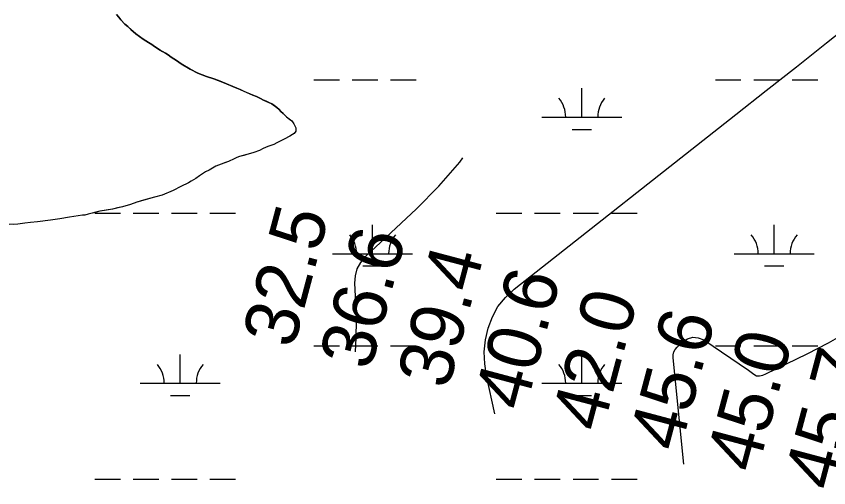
# Model space of a CAD drawing. Extents: x 3192927 to 3230760, y 831141 to 856475.
# Drawn here: x 3214685 to 3215700, y 837451 to 838041 of the extents above; entities that cross this region are included whole.
import ezdxf

# ---------------------------------------------------------------- set-up
doc = ezdxf.new("R2010")
doc.units = 0
for name, color, linetype in [('V-RIVR-RANG', 7, 'Continuous'), ('V-SITE-VEGE', 7, 'Continuous'), ('V-TOPO-MAJR', 7, 'Continuous'), ('V-TOPO-MINR', 7, 'Continuous'), ('V-TOPO-SHOR', 7, 'Continuous'), ('V-WETL-SWMP', 7, 'Continuous')]:
    doc.layers.add(name, color=color, linetype=linetype)

msp = doc.modelspace()

# ---------------------------------------------------------------- linework, layer by layer
at = {"layer": 'V-SITE-VEGE'}
for p, q in [((3214809.9, 838042.9), (3214812.9, 838039.5)), ((3214812.9, 838039.5), (3214815.5, 838036.4)), ((3214815.5, 838036.4), (3214820.3, 838031)), ((3214820.3, 838031), (3214823.9, 838027.7)), ((3214823.9, 838027.7), (3214834.1, 838018.6)), ((3214834.1, 838018.6), (3214838.7, 838015.2)), ((3214838.7, 838015.2), (3214843.3, 838012)), ((3214843.3, 838012), (3214849.9, 838007.7)), ((3214849.9, 838007.7), (3214853.9, 838005.3)), ((3214853.9, 838005.3), (3214857.3, 838003)), ((3214857.3, 838003), (3214867.3, 837996.6)), ((3214867.3, 837996.6), (3214871.1, 837994.5)), ((3214871.1, 837994.5), (3214874.5, 837992.3)), ((3214874.5, 837992.3), (3214878.1, 837989.7)), ((3214878.1, 837989.7), (3214885.1, 837985.4)), ((3214885.1, 837985.4), (3214890.9, 837981.2)), ((3214890.9, 837981.2), (3214901.9, 837974.5)), ((3214901.9, 837974.5), (3214911.6, 837969.6)), ((3214911.6, 837969.6), (3214922.6, 837965.3)), ((3214922.6, 837965.3), (3214931.6, 837962.4)), ((3214931.6, 837962.4), (3214942.4, 837958.2)), ((3214942.4, 837958.2), (3214964.5, 837949)), ((3214964.5, 837949), (3214976.5, 837943.9)), ((3214976.5, 837943.9), (3214980.3, 837942.1)), ((3214980.3, 837942.1), (3214984.9, 837940.2)), ((3214984.9, 837940.2), (3214989.9, 837937.8)), ((3214989.9, 837937.8), (3214993.5, 837935.8)), ((3214993.5, 837935.8), (3215000.5, 837932.9)), ((3215000.5, 837932.9), (3215004.1, 837931.1)), ((3215004.1, 837931.1), (3215010.3, 837926.6)), ((3215010.3, 837926.6), (3215013.3, 837924)), ((3215013.3, 837924), (3215015.5, 837921.6)), ((3215015.5, 837921.6), (3215020.1, 837917.3)), ((3215020.1, 837917.3), (3215022.5, 837914.9)), ((3215022.5, 837914.9), (3215028.9, 837910)), ((3215028.9, 837910), (3215031.7, 837906.2)), ((3215031.7, 837906.2), (3215033.9, 837901.4)), ((3215033.9, 837901.4), (3215034.1, 837897)), ((3215026.4, 837890.8), (3215019.4, 837887.1)), ((3215031.8, 837894), (3215026.4, 837890.8)), ((3215034.1, 837897), (3215031.8, 837894)), ((3215006.5, 837880.5), (3214999.1, 837877.8)), ((3215010.4, 837882.3), (3215006.5, 837880.5)), ((3215019.4, 837887.1), (3215010.4, 837882.3)), ((3214981.7, 837870.3), (3214977.4, 837869.1)), ((3214988.7, 837873), (3214981.7, 837870.3)), ((3214993.3, 837875.4), (3214988.7, 837873)), ((3214999.1, 837877.8), (3214993.3, 837875.4)), ((3214949.8, 837859.3), (3214940.7, 837855.9)), ((3214957, 837862.4), (3214949.8, 837859.3)), ((3214960.4, 837864), (3214957, 837862.4)), ((3214963.8, 837865.2), (3214960.4, 837864)), ((3214973, 837867.7), (3214963.8, 837865.2)), ((3214977.4, 837869.1), (3214973, 837867.7)), ((3214934.1, 837853.1), (3214925.9, 837848.4)), ((3214940.7, 837855.9), (3214934.1, 837853.1)), ((3214913.8, 837841.2), (3214909, 837837.9)), ((3214917.5, 837843.6), (3214913.8, 837841.2)), ((3214921.3, 837846.2), (3214917.5, 837843.6)), ((3214925.9, 837848.4), (3214921.3, 837846.2)), ((3214900, 837832.5), (3214890.2, 837827.8)), ((3214903.4, 837834.5), (3214900, 837832.5)), ((3214906, 837836.3), (3214903.4, 837834.5)), ((3214909, 837837.9), (3214906, 837836.3)), ((3214880.9, 837823), (3214866.9, 837816.9)), ((3214890.2, 837827.8), (3214880.9, 837823)), ((3214857.5, 837814.5), (3214835.2, 837808.1)), ((3214866.9, 837816.9), (3214857.5, 837814.5)), ((3214804.7, 837799.6), (3214788.9, 837796.9)), ((3214817.6, 837802.4), (3214804.7, 837799.6)), ((3214827.6, 837805.5), (3214817.6, 837802.4)), ((3214835.2, 837808.1), (3214827.6, 837805.5)), ((3214751.2, 837789.7), (3214739, 837787.6)), ((3214767.3, 837792), (3214751.2, 837789.7)), ((3214770.5, 837792), (3214767.3, 837792)), ((3214774.5, 837793.4), (3214770.5, 837792)), ((3214788.9, 837796.9), (3214774.5, 837793.4)), ((3214686.5, 837780.7), (3214675.9, 837780.2)), ((3214695.3, 837782), (3214686.5, 837780.7)), ((3214702.4, 837782.8), (3214695.3, 837782)), ((3214711.2, 837783.6), (3214702.4, 837782.8)), ((3214727.2, 837785.7), (3214711.2, 837783.6)), ((3214739, 837787.6), (3214727.2, 837785.7))]:
    msp.add_line(p, q, dxfattribs=at)
at = {"layer": 'V-TOPO-MAJR'}
msp.add_lwpolyline([(3215108.5, 837621.3), (3215109.5, 837638.5), (3215109.7, 837660.6), (3215109.1, 837682.6), (3215107.8, 837707.1), (3215108.6, 837716.4), (3215110.9, 837725.1), (3215115.3, 837732.9), (3215121.2, 837740.2), (3215184.8, 837799.9), (3215212.8, 837828.5), (3215239, 837858.5), (3215242.7, 837863.6)], dxfattribs=at)
at = {"layer": 'V-TOPO-MINR'}
for points in [[(3215282.7, 837543.5), (3215272.3, 837591.3), (3215270.2, 837606.2), (3215269.6, 837621.2), (3215271.2, 837636), (3215274.3, 837650.8), (3215279.7, 837664.8), (3215286.7, 837677.7), (3215296, 837689), (3215306.8, 837699.4), (3215584, 837917.8), (3215621.9, 837947.7), (3215659.7, 837977.6), (3215697.6, 838007.6), (3215735.4, 838037.5)], [(3215519.1, 837480.9), (3215505.8, 837613.9), (3215505.9, 837617.6), (3215506.7, 837621.1), (3215508.4, 837624.3), (3215510.6, 837627.2), (3215517.3, 837633.7), (3215523.7, 837637.6), (3215530.2, 837639.6), (3215537, 837638.8), (3215543.9, 837636), (3215599.7, 837598.2), (3215603.2, 837595.8), (3215606.6, 837593.1), (3215610.1, 837591.2), (3215613.7, 837591.1), (3215617.9, 837592.2), (3215621.7, 837593.7), (3215673.4, 837618.7), (3215700, 837632.5), (3215726, 837647.4)]]:
    msp.add_lwpolyline(points, dxfattribs=at)
at = {"layer": 'V-TOPO-SHOR'}
for points in [[(3215020.1, 837917.3), (3215018.1, 837919.2), (3215015.5, 837921.6), (3215013.3, 837924), (3215010.3, 837926.6), (3215006.9, 837929.1), (3215004.1, 837931.1), (3215000.5, 837932.9), (3214996.9, 837934.5), (3214993.5, 837935.8), (3214989.9, 837937.8), (3214984.9, 837940.2), (3214980.3, 837942.1), (3214976.5, 837943.9), (3214970.5, 837946.4), (3214964.5, 837949), (3214960.3, 837950.8), (3214955.5, 837952.7), (3214947.2, 837956.3), (3214942.4, 837958.2), (3214937.2, 837960.2), (3214931.6, 837962.4), (3214922.6, 837965.3), (3214911.6, 837969.6), (3214901.9, 837974.5), (3214890.9, 837981.2), (3214885.1, 837985.4), (3214878.1, 837989.7), (3214874.5, 837992.3), (3214871.1, 837994.5), (3214867.3, 837996.6), (3214864.5, 837998.4), (3214857.3, 838003), (3214853.9, 838005.3), (3214849.9, 838007.7), (3214843.3, 838012), (3214838.7, 838015.2), (3214834.1, 838018.6), (3214827.9, 838024.1), (3214823.9, 838027.7), (3214820.3, 838031), (3214815.5, 838036.4), (3214812.9, 838039.5), (3214809.9, 838042.9)], [(3215020.1, 837917.3), (3215022.5, 837914.9), (3215026.1, 837912.1), (3215028.9, 837910), (3215031.7, 837906.2), (3215033.9, 837901.4), (3215034.1, 837897), (3215031.8, 837894), (3215029.2, 837892.4), (3215026.4, 837890.8), (3215019.4, 837887.1), (3215016, 837885.3), (3215010.4, 837882.3), (3215006.5, 837880.5), (3215002.9, 837879.2), (3214999.1, 837877.8), (3214993.3, 837875.4), (3214988.7, 837873), (3214981.7, 837870.3), (3214977.4, 837869.1), (3214973, 837867.7), (3214969, 837866.7), (3214963.8, 837865.2), (3214960.4, 837864), (3214957, 837862.4), (3214949.8, 837859.3), (3214944.8, 837857.5), (3214940.7, 837855.9), (3214934.1, 837853.1), (3214930.1, 837850.8), (3214925.9, 837848.4), (3214921.3, 837846.2), (3214917.5, 837843.6), (3214913.8, 837841.2), (3214909, 837837.9), (3214906, 837836.3), (3214903.4, 837834.5), (3214900, 837832.5), (3214890.2, 837827.8), (3214880.9, 837823), (3214866.9, 837816.9), (3214857.5, 837814.5), (3214843.8, 837810.6), (3214835.2, 837808.1), (3214827.6, 837805.5), (3214817.6, 837802.4), (3214811.3, 837801), (3214804.7, 837799.6), (3214794.9, 837797.9), (3214788.9, 837796.9), (3214783.1, 837795.4), (3214774.5, 837793.4), (3214770.5, 837792), (3214767.3, 837792), (3214751.2, 837789.7), (3214739, 837787.6), (3214727.2, 837785.7), (3214711.2, 837783.6), (3214702.4, 837782.8), (3214695.3, 837782), (3214686.5, 837780.7), (3214681.7, 837780.5)]]:
    msp.add_lwpolyline(points, dxfattribs=at)
at = {"layer": 'V-WETL-SWMP'}
for p, q in [((3214809.9, 838042.9), (3214812.9, 838039.5)), ((3214812.9, 838039.5), (3214815.5, 838036.4)), ((3214815.5, 838036.4), (3214820.3, 838031)), ((3214820.3, 838031), (3214823.9, 838027.7)), ((3214823.9, 838027.7), (3214827.9, 838024.1)), ((3214827.9, 838024.1), (3214834.1, 838018.6)), ((3214834.1, 838018.6), (3214838.7, 838015.2)), ((3214838.7, 838015.2), (3214843.3, 838012)), ((3214843.3, 838012), (3214849.9, 838007.7)), ((3214849.9, 838007.7), (3214853.9, 838005.3)), ((3214853.9, 838005.3), (3214857.3, 838003)), ((3214857.3, 838003), (3214864.5, 837998.4)), ((3214864.5, 837998.4), (3214867.3, 837996.6)), ((3214867.3, 837996.6), (3214871.1, 837994.5)), ((3214871.1, 837994.5), (3214874.5, 837992.3)), ((3214874.5, 837992.3), (3214878.1, 837989.7)), ((3214878.1, 837989.7), (3214885.1, 837985.4)), ((3214885.1, 837985.4), (3214890.9, 837981.2)), ((3214890.9, 837981.2), (3214901.9, 837974.5)), ((3214901.9, 837974.5), (3214911.6, 837969.6)), ((3214911.6, 837969.6), (3214922.6, 837965.3)), ((3214922.6, 837965.3), (3214931.6, 837962.4)), ((3214931.6, 837962.4), (3214937.2, 837960.2)), ((3215056.6, 837961.1), (3215088.6, 837961.1)), ((3215104.6, 837961.1), (3215136.6, 837961.1)), ((3215152.6, 837961.1), (3215184.6, 837961.1)), ((3215558.5, 837961.1), (3215590.5, 837961.1)), ((3215606.5, 837961.1), (3215638.5, 837961.1)), ((3215654.5, 837961.1), (3215686.5, 837961.1)), ((3214937.2, 837960.2), (3214942.4, 837958.2)), ((3214942.4, 837958.2), (3214947.2, 837956.3)), ((3214947.2, 837956.3), (3214955.5, 837952.7)), ((3214955.5, 837952.7), (3214960.3, 837950.8)), ((3214960.3, 837950.8), (3214964.5, 837949)), ((3215391.5, 837914.7), (3215391.5, 837950.7)), ((3214964.5, 837949), (3214976.5, 837943.9)), ((3214976.5, 837943.9), (3214980.3, 837942.1)), ((3214980.3, 837942.1), (3214984.9, 837940.2)), ((3214984.9, 837940.2), (3214989.9, 837937.8)), ((3214989.9, 837937.8), (3214993.5, 837935.8)), ((3214993.5, 837935.8), (3214996.9, 837934.5)), ((3214996.9, 837934.5), (3215000.5, 837932.9)), ((3215000.5, 837932.9), (3215004.1, 837931.1)), ((3215004.1, 837931.1), (3215006.9, 837929.1)), ((3215006.9, 837929.1), (3215010.3, 837926.6)), ((3215010.3, 837926.6), (3215013.3, 837924)), ((3215013.3, 837924), (3215015.5, 837921.6)), ((3215015.5, 837921.6), (3215018.1, 837919.2)), ((3215018.1, 837919.2), (3215020.1, 837917.3)), ((3215020.1, 837917.3), (3215022.5, 837914.9)), ((3215022.5, 837914.9), (3215026.1, 837912.1)), ((3215026.1, 837912.1), (3215028.9, 837910)), ((3215028.9, 837910), (3215031.7, 837906.2)), ((3215341.5, 837914.7), (3215441.5, 837914.7)), ((3215031.7, 837906.2), (3215033.9, 837901.4)), ((3215033.9, 837901.4), (3215034.1, 837897)), ((3215026.4, 837890.8), (3215019.4, 837887.1)), ((3215029.2, 837892.4), (3215026.4, 837890.8)), ((3215031.8, 837894), (3215029.2, 837892.4)), ((3215034.1, 837897), (3215031.8, 837894)), ((3215379.5, 837899.3), (3215403.5, 837899.3)), ((3215006.5, 837880.5), (3215002.9, 837879.2)), ((3215010.4, 837882.3), (3215006.5, 837880.5)), ((3215016, 837885.3), (3215010.4, 837882.3)), ((3215019.4, 837887.1), (3215016, 837885.3)), ((3214981.7, 837870.3), (3214977.3, 837869.1)), ((3214988.7, 837873), (3214981.7, 837870.3)), ((3214993.3, 837875.4), (3214988.7, 837873)), ((3214999.1, 837877.8), (3214993.3, 837875.4)), ((3215002.9, 837879.2), (3214999.1, 837877.8)), ((3214949.8, 837859.3), (3214944.8, 837857.5)), ((3214957, 837862.4), (3214949.8, 837859.3)), ((3214960.4, 837864), (3214957, 837862.4)), ((3214963.8, 837865.2), (3214960.4, 837864)), ((3214969, 837866.7), (3214963.8, 837865.2)), ((3214973, 837867.7), (3214969, 837866.7)), ((3214977.3, 837869.1), (3214973, 837867.7)), ((3214930.1, 837850.8), (3214925.9, 837848.4)), ((3214934.1, 837853.1), (3214930.1, 837850.8)), ((3214940.7, 837855.9), (3214934.1, 837853.1)), ((3214944.8, 837857.5), (3214940.7, 837855.9)), ((3214913.8, 837841.2), (3214909, 837837.9)), ((3214917.5, 837843.6), (3214913.8, 837841.2)), ((3214921.3, 837846.2), (3214917.5, 837843.6)), ((3214925.9, 837848.4), (3214921.3, 837846.2)), ((3214900, 837832.5), (3214890.2, 837827.8)), ((3214903.4, 837834.5), (3214900, 837832.5)), ((3214906, 837836.3), (3214903.4, 837834.5)), ((3214909, 837837.9), (3214906, 837836.3)), ((3214880.9, 837823), (3214866.9, 837816.9)), ((3214890.2, 837827.8), (3214880.9, 837823)), ((3214843.8, 837810.6), (3214835.2, 837808.1)), ((3214857.5, 837814.5), (3214843.8, 837810.6)), ((3214866.9, 837816.9), (3214857.5, 837814.5)), ((3214804.7, 837799.6), (3214794.9, 837797.9)), ((3214811.3, 837801), (3214804.7, 837799.6)), ((3214817.6, 837802.4), (3214811.3, 837801)), ((3214827.6, 837805.5), (3214817.6, 837802.4)), ((3214835.2, 837808.1), (3214827.6, 837805.5)), ((3214751.2, 837789.7), (3214739, 837787.6)), ((3214767.3, 837792), (3214751.2, 837789.7)), ((3214770.5, 837792), (3214767.3, 837792)), ((3214774.5, 837793.4), (3214770.5, 837792)), ((3214783.1, 837795.4), (3214774.5, 837793.4)), ((3214782.7, 837794.6), (3214814.7, 837794.6)), ((3214788.9, 837796.9), (3214783.1, 837795.4)), ((3214794.9, 837797.9), (3214788.9, 837796.9)), ((3214830.7, 837794.6), (3214862.7, 837794.6)), ((3214878.7, 837794.6), (3214910.7, 837794.6)), ((3214926.7, 837794.6), (3214958.7, 837794.6)), ((3215284.6, 837794.6), (3215316.6, 837794.6)), ((3215332.6, 837794.6), (3215364.6, 837794.6)), ((3215380.6, 837794.6), (3215412.6, 837794.6)), ((3215428.6, 837794.6), (3215460.6, 837794.6)), ((3214686.5, 837780.7), (3214681.7, 837780.5)), ((3214695.3, 837782), (3214686.5, 837780.7)), ((3214702.4, 837782.8), (3214695.3, 837782)), ((3214711.2, 837783.6), (3214702.4, 837782.8)), ((3214727.2, 837785.7), (3214711.2, 837783.6)), ((3214739, 837787.6), (3214727.2, 837785.7)), ((3215130, 837743.9), (3215130, 837779.9)), ((3215631.9, 837743.9), (3215631.9, 837779.9)), ((3215080, 837743.9), (3215180, 837743.9)), ((3215581.9, 837743.9), (3215681.9, 837743.9)), ((3215118, 837728.5), (3215142, 837728.5)), ((3215619.9, 837728.5), (3215643.9, 837728.5)), ((3215056.6, 837628.5), (3215088.6, 837628.5)), ((3215104.6, 837628.5), (3215136.6, 837628.5)), ((3215152.6, 837628.5), (3215184.6, 837628.5)), ((3215558.5, 837628.5), (3215590.5, 837628.5)), ((3215606.5, 837628.5), (3215638.5, 837628.5)), ((3215654.5, 837628.5), (3215686.5, 837628.5)), ((3214889.6, 837582), (3214889.6, 837618)), ((3215391.5, 837582), (3215391.5, 837618)), ((3214839.6, 837582), (3214939.6, 837582)), ((3215341.5, 837582), (3215441.5, 837582)), ((3214877.6, 837566.6), (3214901.6, 837566.6)), ((3215379.5, 837566.6), (3215403.5, 837566.6)), ((3214782.7, 837462), (3214814.7, 837462)), ((3214830.7, 837462), (3214862.7, 837462)), ((3214878.7, 837462), (3214910.7, 837462)), ((3214926.7, 837462), (3214958.7, 837462)), ((3215284.6, 837462), (3215316.6, 837462)), ((3215332.6, 837462), (3215364.6, 837462)), ((3215380.6, 837462), (3215412.6, 837462)), ((3215428.6, 837462), (3215460.6, 837462))]:
    msp.add_line(p, q, dxfattribs=at)
for centre, start, end in [((3215336.2, 837915.2), 359.2282, 40.7718), ((3215446.7, 837915.2), 139.2282, 180.7718), ((3215074.8, 837744.4), 359.2282, 40.7718), ((3215185.3, 837744.4), 139.2282, 180.7718), ((3215576.7, 837744.4), 359.2282, 40.7718), ((3215687.2, 837744.4), 139.2282, 180.7718), ((3214834.3, 837582.5), 359.2282, 40.7718), ((3214944.8, 837582.5), 139.2282, 180.7718), ((3215336.2, 837582.5), 359.2282, 40.7718), ((3215446.7, 837582.5), 139.2282, 180.7718)]:
    msp.add_arc(centre, 35.2, start, end, dxfattribs=at)

# ---------------------------------------------------------------- texts
at = {"layer": 'V-RIVR-RANG'}
for s, p in [('32.5', (3215031, 837623.9)), ('36.6', (3215127.2, 837596.6)), ('39.4', (3215224.4, 837572.9)), ('40.6', (3215320.6, 837545.6)), ('42.0', (3215417, 837519.1)), ('45.6', (3215514, 837494.6)), ('45.0', (3215610.4, 837468.1)), ('45.7', (3215707.8, 837445.4))]:
    msp.add_text(s, height=67, rotation=75.0883, dxfattribs=at).set_placement(p)

doc.saveas('drawing.dxf')
